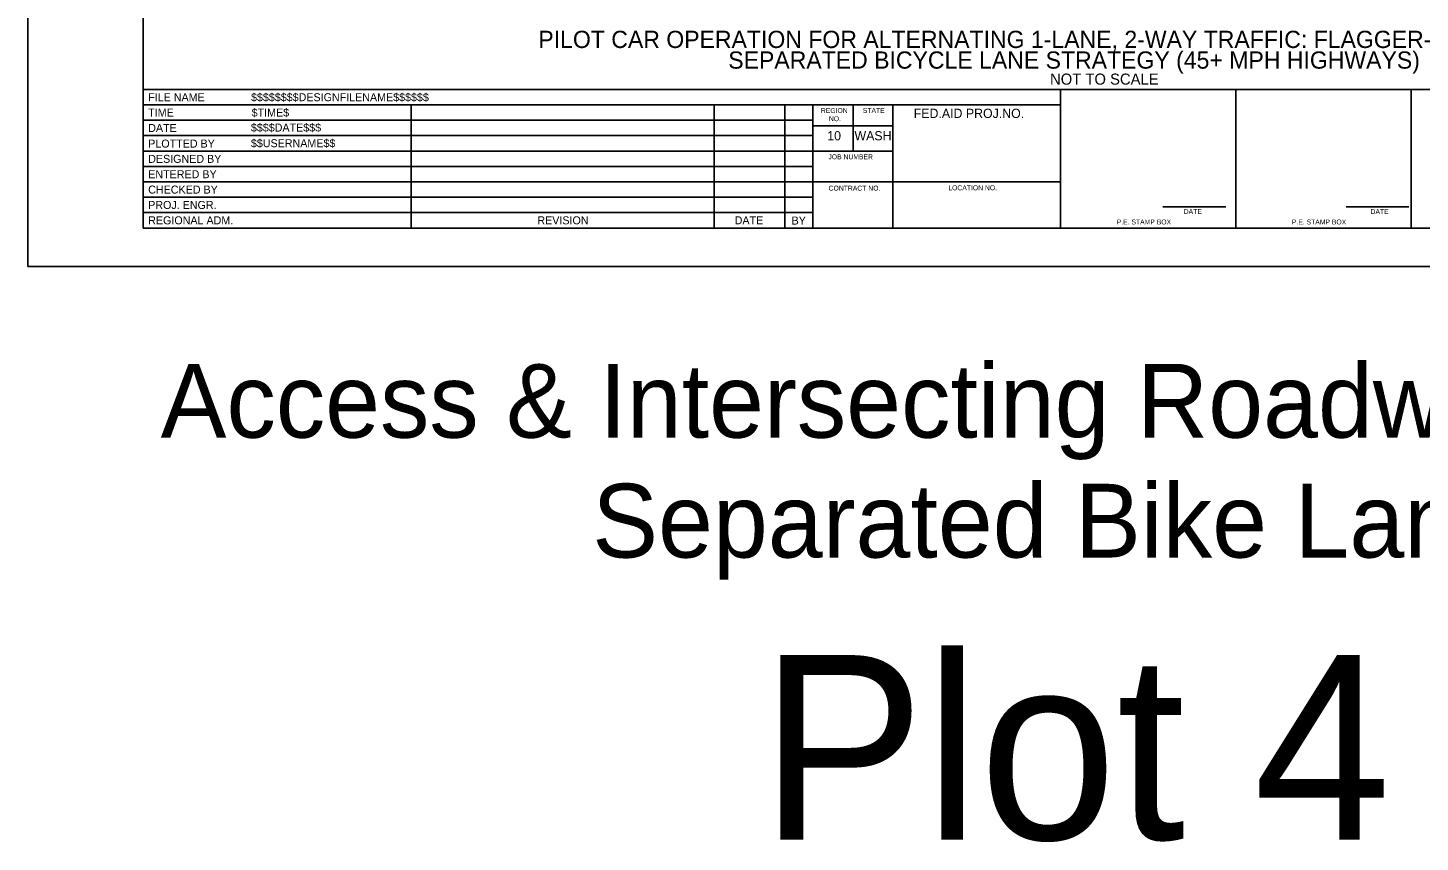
# Model space of a CAD drawing. Extents: x 99999.1 to 100095.7, y 99995 to 100010.7.
# Drawn here: x 100059.06 to 100070.38, y 99995.01 to 100001.63 of the extents above; entities that cross this region are included whole.
import ezdxf

# ---------------------------------------------------------------- set-up
doc = ezdxf.new("R2010")
doc.units = 0
for name, color, linetype in [('SH_DE_DetailHeading1Text', 7, 'Continuous'), ('SH_GI_PlotLimits', 7, 'Continuous'), ('SH_GI_SheetBorder', 7, 'Continuous'), ('SH_GI_SheetLocationText', 7, 'Continuous'), ('SH_GI_SheetTextInCells', 7, 'Continuous'), ('SH_GI_TitleBlockText', 7, 'Continuous')]:
    doc.layers.add(name, color=color, linetype=linetype)

msp = doc.modelspace()

# ---------------------------------------------------------------- linework, layer by layer
at = {"layer": 'SH_GI_PlotLimits'}
msp.add_lwpolyline([(100059.062, 99999.687), (100076.062, 99999.687), (100076.062, 100010.687), (100059.062, 100010.687)], close=True, dxfattribs=at)
at = {"layer": 'SH_GI_SheetBorder'}
for p, q in [((100060, 100010.375), (100060, 100000)), ((100060, 100001.126), (100075.75, 100001.126)), ((100067.457, 100000), (100067.457, 100001.126)), ((100068.883, 100000), (100068.883, 100001.126)), ((100070.309, 100001.126), (100070.309, 100000)), ((100060, 100001.001), (100067.457, 100001.001)), ((100062.179, 100001.001), (100062.179, 100000)), ((100064.641, 100001.001), (100064.641, 100000)), ((100065.216, 100001.001), (100065.216, 100000)), ((100065.445, 100001.001), (100065.445, 100000)), ((100065.772, 100000.625), (100065.772, 100001.001)), ((100066.096, 100000), (100066.096, 100001.001)), ((100060, 100000.876), (100062.182, 100000.876)), ((100062.182, 100000.876), (100065.447, 100000.876)), ((100060, 100000.751), (100062.182, 100000.751)), ((100062.182, 100000.751), (100065.447, 100000.751)), ((100066.096, 100000.831), (100065.447, 100000.831)), ((100060, 100000.625), (100065.447, 100000.625)), ((100066.096, 100000.625), (100065.447, 100000.625)), ((100060, 100000.5), (100065.447, 100000.5)), ((100060, 100000.375), (100065.447, 100000.375)), ((100067.457, 100000.375), (100065.447, 100000.375)), ((100060, 100000.25), (100065.447, 100000.25)), ((100060, 100000.125), (100065.447, 100000.125)), ((100068.29, 100000.173), (100068.802, 100000.173)), ((100069.78, 100000.173), (100070.291, 100000.173)), ((100060, 100000), (100075.75, 100000))]:
    msp.add_line(p, q, dxfattribs=at)

# ---------------------------------------------------------------- texts
at = {"layer": 'SH_DE_DetailHeading1Text'}
for s, height, p in [('PILOT CAR OPERATION FOR ALTERNATING 1-LANE, 2-WAY TRAFFIC: FLAGGER-CONTROLLED', 0.14, (100063.213, 100001.464)), ('SEPARATED BICYCLE LANE STRATEGY (45+ MPH HIGHWAYS)', 0.14, (100064.757, 100001.296)), ('NOT TO SCALE', 0.09, (100067.373, 100001.166))]:
    msp.add_text(s, height=height, rotation=360, dxfattribs=at).set_placement(p)
at = {"layer": 'SH_GI_SheetLocationText'}
for s, height, p in [('Access & Intersecting Roadway Details', 0.6, (100060.142, 99998.295)), ('Separated Bike Lane', 0.6, (100063.651, 99997.32)), ('Plot 4', 1.5, (100065.015, 99995.027))]:
    msp.add_text(s, height=height, dxfattribs=at).set_placement(p)
at = {"layer": 'SH_GI_SheetTextInCells'}
for s, height, p in [('FILE NAME', 0.0651, (100060.041, 100001.031)), ('REGION', 0.04, (100065.51, 100000.935)), ('STATE', 0.04, (100065.851, 100000.936)), ('TIME', 0.0651, (100060.041, 100000.906)), ('NO.', 0.04, (100065.575, 100000.869)), ('FED.AID PROJ.NO.', 0.07506, (100066.265, 100000.895)), ('DATE', 0.0651, (100060.041, 100000.781)), ('10', 0.0751, (100065.562, 100000.713)), ('WASH', 0.0751, (100065.783, 100000.713)), ('PLOTTED BY', 0.0651, (100060.041, 100000.654)), ('DESIGNED BY', 0.06505, (100060.041, 100000.53)), ('JOB NUMBER', 0.04, (100065.571, 100000.559)), ('ENTERED BY', 0.0651, (100060.041, 100000.405)), ('CHECKED BY', 0.0651, (100060.041, 100000.28)), ('CONTRACT NO.', 0.04003, (100065.573, 100000.304)), ('LOCATION NO.', 0.04003, (100066.546, 100000.307)), ('PROJ. ENGR.', 0.06505, (100060.041, 100000.155)), ('REGIONAL ADM.', 0.06505, (100060.041, 100000.03)), ('REVISION', 0.0651, (100063.205, 100000.03)), ('DATE', 0.0651, (100064.809, 100000.03)), ('BY', 0.0651, (100065.272, 100000.028)), ('P.E. STAMP BOX', 0.04003, (100067.915, 100000.029)), ('DATE', 0.04, (100068.46, 100000.114)), ('P.E. STAMP BOX', 0.04003, (100069.339, 100000.029)), ('DATE', 0.04, (100069.979, 100000.114))]:
    msp.add_text(s, height=height, dxfattribs=at).set_placement(p)
at = {"layer": 'SH_GI_TitleBlockText'}
for s, height, p in [('$$$$$$$$DESIGNFILENAME$$$$$$', 0.06505, (100060.877, 100001.031)), ('$TIME$', 0.0651, (100060.882, 100000.906)), ('$$$$DATE$$$', 0.06505, (100060.876, 100000.784)), ('$$USERNAME$$', 0.06505, (100060.876, 100000.657))]:
    msp.add_text(s, height=height, dxfattribs=at).set_placement(p)

doc.saveas('drawing.dxf')
